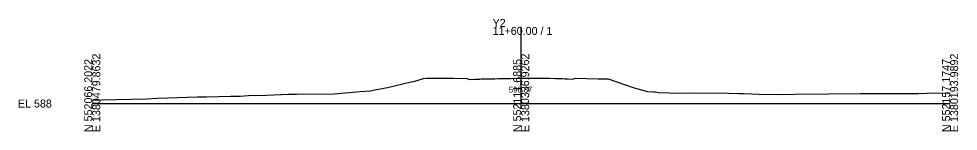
# Model space of a CAD drawing. Extents: x -26 to 303, y -10 to 2047.
# Drawn here: x -25.7 to 302.8, y 1490.3 to 1529.7 of the extents above; entities that cross this region are included whole.
import ezdxf

# ---------------------------------------------------------------- set-up
doc = ezdxf.new("R2010")
doc.units = 0
for name, color, linetype in [('Exist Cross Section Cell', 7, 'Continuous'), ('Exist XS Center Line Elevation Label', 7, 'Continuous'), ('Exist XS Ground Line', 7, 'Continuous')]:
    doc.layers.add(name, color=color, linetype=linetype)

msp = doc.modelspace()

# ---------------------------------------------------------------- linework, layer by layer
at = {"layer": 'Exist Cross Section Cell'}
for p, q in [((150, 1500), (150, 1526.83)), ((0, 1500), (150, 1500)), ((150, 1500), (300, 1500))]:
    msp.add_line(p, q, dxfattribs=at)
at = {"layer": 'Exist XS Ground Line'}
for p, q in [((112.41, 1507.76), (115.85, 1508.73)), ((115.85, 1508.73), (116.93, 1508.91)), ((116.93, 1508.91), (126.36, 1508.87)), ((126.36, 1508.87), (131.04, 1508.82)), ((131.04, 1508.82), (131.9, 1508.45)), ((131.9, 1508.45), (133.76, 1508.52)), ((133.76, 1508.52), (135.6, 1508.59)), ((135.6, 1508.59), (136.01, 1508.6)), ((136.01, 1508.6), (137.3, 1508.63)), ((137.3, 1508.63), (138.23, 1508.64)), ((138.23, 1508.64), (138.66, 1508.65)), ((138.66, 1508.65), (140.84, 1508.69)), ((140.84, 1508.69), (141.98, 1508.71)), ((141.98, 1508.71), (143.48, 1508.73)), ((143.48, 1508.73), (143.97, 1508.74)), ((143.97, 1508.74), (145.53, 1508.78)), ((145.53, 1508.78), (146.38, 1508.8)), ((146.38, 1508.8), (148.72, 1508.86)), ((148.72, 1508.86), (150.19, 1508.87)), ((150.19, 1508.87), (151.32, 1508.88)), ((151.32, 1508.88), (153.93, 1508.88)), ((153.93, 1508.88), (155.87, 1508.88)), ((155.87, 1508.88), (156.55, 1508.88)), ((156.55, 1508.88), (157.86, 1508.88)), ((157.86, 1508.88), (159.18, 1508.86)), ((159.18, 1508.86), (159.86, 1508.84)), ((159.86, 1508.84), (162.03, 1508.79)), ((162.03, 1508.79), (164.43, 1508.72)), ((164.43, 1508.72), (165.29, 1508.7)), ((165.29, 1508.7), (166.25, 1508.67)), ((166.25, 1508.67), (168.07, 1508.55)), ((168.07, 1508.55), (168.9, 1508.94)), ((168.9, 1508.94), (176.95, 1508.69)), ((176.95, 1508.69), (179.24, 1508.63)), ((179.24, 1508.63), (180.45, 1508.61)), ((180.45, 1508.61), (183.13, 1507.71)), ((97.28, 1504.49), (98.2, 1504.71)), ((98.2, 1504.71), (103.26, 1505.61)), ((103.26, 1505.61), (111.54, 1507.57)), ((111.54, 1507.57), (112.41, 1507.76)), ((183.13, 1507.71), (189.55, 1505.5)), ((189.55, 1505.5), (194.14, 1504.24)), ((3.13, 1501.31), (19.12, 1501.7)), ((19.12, 1501.7), (22.87, 1501.93)), ((22.87, 1501.93), (36.64, 1502.34)), ((36.64, 1502.34), (37.06, 1502.36)), ((37.06, 1502.36), (39.78, 1502.39)), ((39.78, 1502.39), (48.46, 1502.59)), ((48.46, 1502.59), (51.67, 1502.62)), ((51.67, 1502.62), (54.59, 1502.78)), ((54.59, 1502.78), (60.95, 1502.9)), ((60.95, 1502.9), (68.54, 1503.24)), ((68.54, 1503.24), (71.46, 1503.23)), ((71.46, 1503.23), (84.63, 1503.44)), ((84.63, 1503.44), (93.7, 1504.17)), ((93.7, 1504.17), (97.28, 1504.49)), ((194.14, 1504.24), (196.26, 1504.13)), ((196.26, 1504.13), (196.88, 1504.07)), ((196.88, 1504.07), (198.12, 1503.89)), ((198.12, 1503.89), (205.42, 1503.64)), ((205.42, 1503.64), (210.21, 1503.72)), ((210.21, 1503.72), (222.54, 1503.61)), ((222.54, 1503.61), (225.95, 1503.53)), ((225.95, 1503.53), (227.76, 1503.48)), ((227.76, 1503.48), (233.27, 1503.32)), ((233.27, 1503.32), (241.7, 1503.2)), ((241.7, 1503.2), (245.63, 1503.23)), ((245.63, 1503.23), (257.44, 1503.4)), ((257.44, 1503.4), (268.72, 1503.49)), ((268.72, 1503.49), (273.18, 1503.55)), ((273.18, 1503.55), (282.73, 1503.5)), ((282.73, 1503.5), (288.92, 1503.5)), ((288.92, 1503.5), (291.81, 1503.58)), ((291.81, 1503.58), (300, 1503.73)), ((0, 1501.18), (3.13, 1501.31))]:
    msp.add_line(p, q, dxfattribs=at)

# ---------------------------------------------------------------- texts
at = {"layer": 'Exist Cross Section Cell'}
for s, p in [('Y2', (140, 1526.83)), ('11+60.00 / 1', (140, 1524.03)), ('EL 588', (-26, 1498.6))]:
    msp.add_text(s, height=2.8, dxfattribs=at).set_placement(p)
for s, p in [('N 552066.2022', (0, 1490)), ('E 1380479.8632', (2.8, 1490)), ('N 552111.6885', (150, 1490)), ('E 1380336.9262', (152.8, 1490)), ('N 552157.1747', (300, 1490)), ('E 1380193.9892', (302.8, 1490))]:
    msp.add_text(s, height=2.8, rotation=90, dxfattribs=at).set_placement(p)
at = {"layer": 'Exist XS Center Line Elevation Label'}
msp.add_text('596.87', height=2, dxfattribs=at).set_placement((145.7, 1503.87))

doc.saveas('drawing.dxf')
